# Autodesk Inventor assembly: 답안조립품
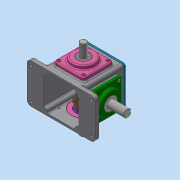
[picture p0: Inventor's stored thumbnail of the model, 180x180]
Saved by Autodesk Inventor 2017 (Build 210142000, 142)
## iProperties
Part Number: 답안조립품
Material: 일반
Document SubType Name: Assembly
Designer: user
Author: user
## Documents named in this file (16)
- C:\Users\MRC\Desktop\620307V1004\답안조립품.iam
- C:\Users\MRC\Desktop\620307V1004\본체.ipt
- C:\Users\MRC\Desktop\620307V1004\개스킷.ipt
- C:\Users\MRC\Desktop\620307V1004\메인베벨기어.ipt
- C:\Users\MRC\Desktop\620307V1004\메인축.ipt
- C:\Users\MRC\Desktop\620307V1004\메인커버.ipt
- C:\Users\MRC\Desktop\620307V1004\베어링 6203.ipt
- C:\Users\MRC\Desktop\620307V1004\베어링 6204.ipt
- C:\Users\MRC\Desktop\620307V1004\볼트 M4.ipt
- C:\Users\MRC\Desktop\620307V1004\상부커버.ipt
- C:\Users\MRC\Desktop\620307V1004\서브베벨기어.ipt
- C:\Users\MRC\Desktop\620307V1004\서브축.ipt
- C:\Users\MRC\Desktop\620307V1004\서브커버.ipt
- C:\Users\MRC\Desktop\620307V1004\오일 실 17 32 8.ipt
- C:\Users\MRC\Desktop\620307V1004\오일 실 20 35 8.ipt
- C:\Users\MRC\Desktop\620307V1004\키 4x4.ipt
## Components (1 placed, 1 different names)
1. 개스킷:1
